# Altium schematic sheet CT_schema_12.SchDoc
size 382 x 278 mm
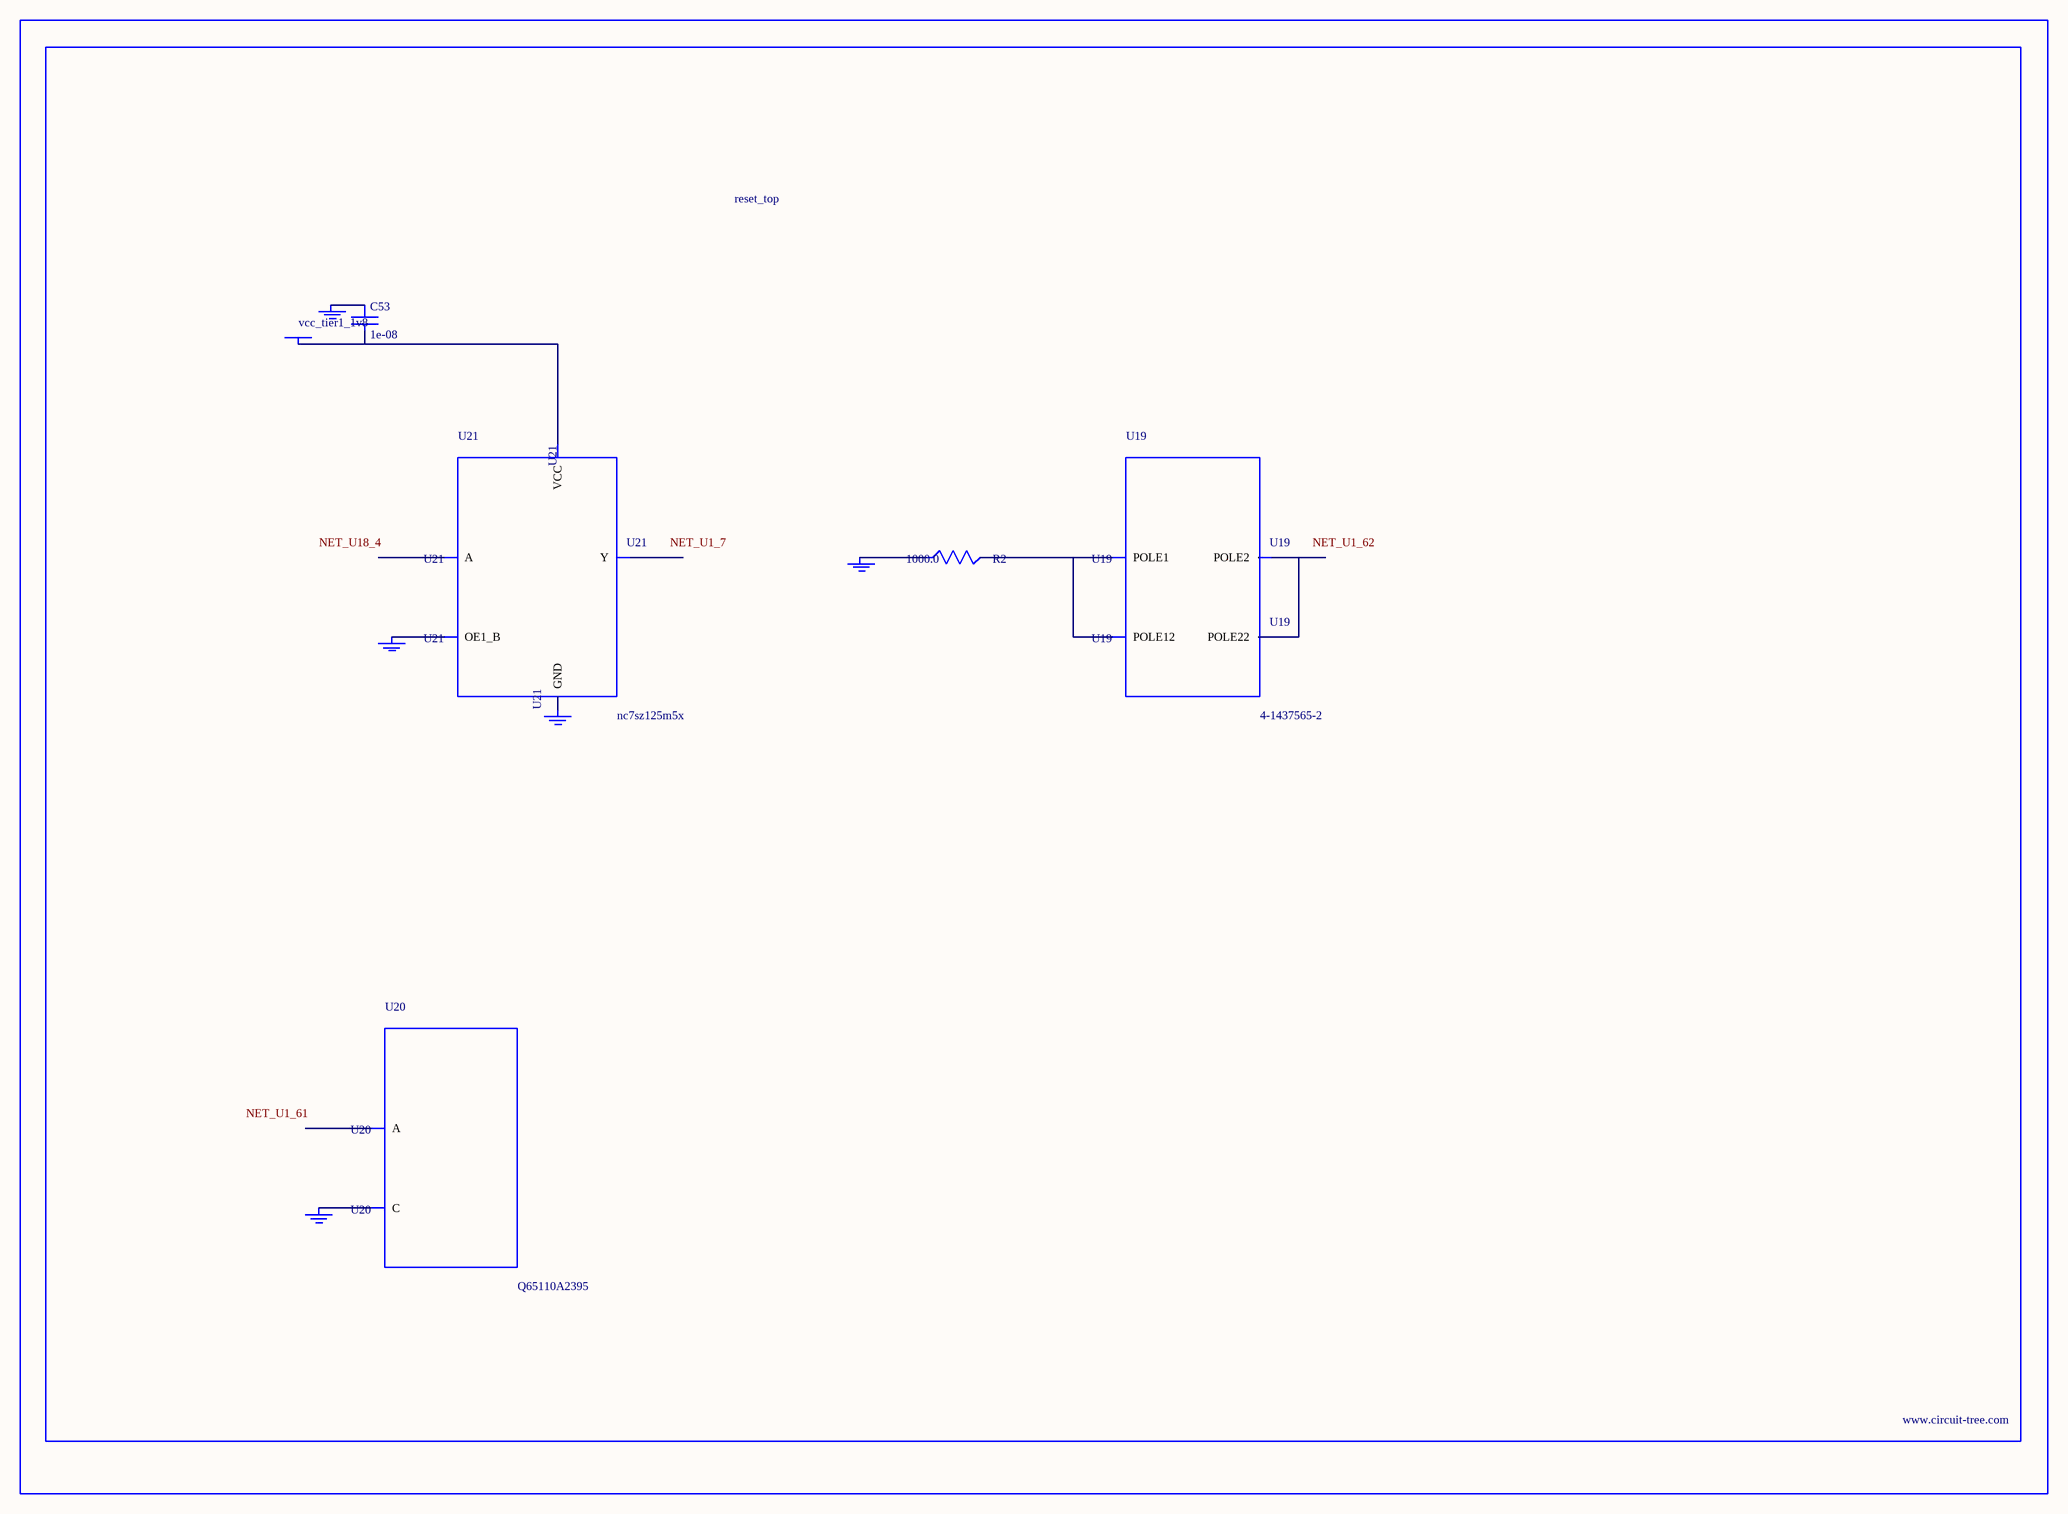
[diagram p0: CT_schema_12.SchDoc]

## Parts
BORDER11  (no value)
C53  1e-08  [C0402]
GND_INSTANCE_11_0  (no value)
GND_INSTANCE_11_1  (no value)
GND_INSTANCE_11_2  (no value)
GND_INSTANCE_11_3  (no value)
GND_INSTANCE_11_4  (no value)
POWER_INSTANCE_11_0  vcc_tier1_1v8
R2  1000.0  [R0603]
U19  4-1437565-2  [SW_4-1437565-2]
U20  Q65110A2395  [LGM67K-G1J2-24-Z]
U21  nc7sz125m5x  [NC7SZ125M5X]

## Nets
NetC53_1: C53.1 GND_INSTANCE_11_2.0(GND)
NetC53_2: C53.2 POWER_INSTANCE_11_0.0(PWR) U21.5(VCC)
NetGND_INSTANCE_11_0_0: GND_INSTANCE_11_0.0(GND) R2.1
NetGND_INSTANCE_11_1_0: GND_INSTANCE_11_1.0(GND) U20.C
NetGND_INSTANCE_11_3_0: GND_INSTANCE_11_3.0(GND) U21.1(OE1_B)
NetGND_INSTANCE_11_4_0: GND_INSTANCE_11_4.0(GND) U21.3(GND)
NetR2_2: R2.2 U19.1(POLE1) U19.2(POLE12)
NetU19_3: U19.3(POLE2) U19.4(POLE22)

Not connected (* = marked no-connect by the designer): U20 A; U21 2(A) 4(Y)

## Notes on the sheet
- Labels drawn without touching a wire or pin: NET_U1_7, NET_U1_61, NET_U1_62, NET_U18_4

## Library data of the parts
BORDER11 = BORDER_PAGE11
C53 = C0402C103K3RAC
GND_INSTANCE_11_0-GND_INSTANCE_11_4 = GND
POWER_INSTANCE_11_0 = PWR
R2 = RC0603JR-071KL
